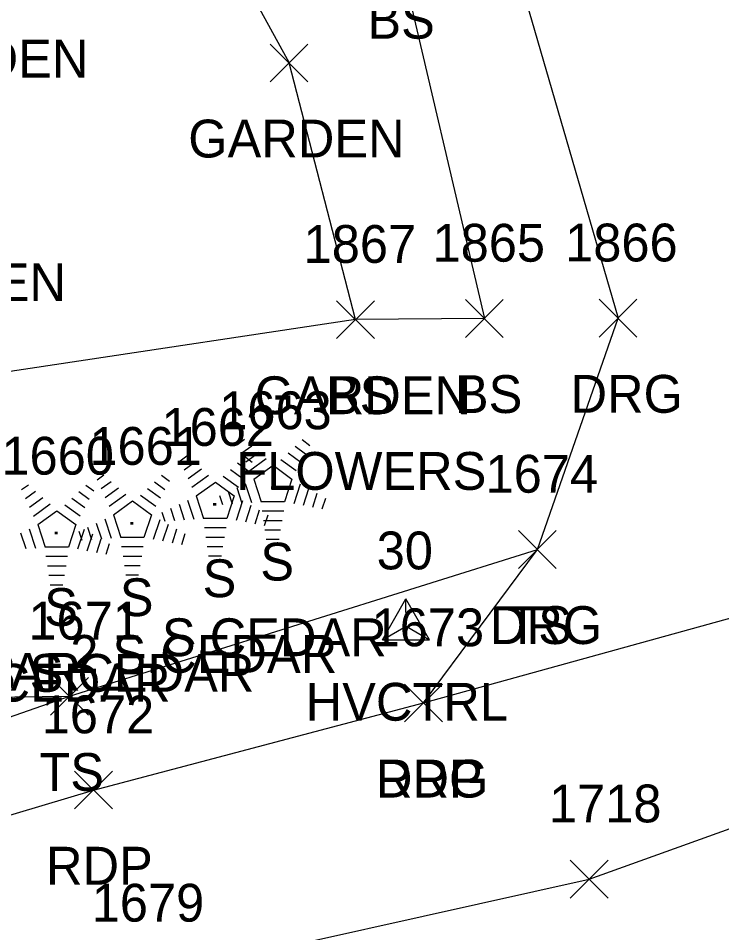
# Model space of a CAD drawing. Extents: x 1499292 to 1501024, y 534584 to 538043.
# Drawn here: x 1499990.32 to 1500027.52, y 537630.09 to 537678.44 of the extents above; entities that cross this region are included whole.
import ezdxf

# ---------------------------------------------------------------- set-up
doc = ezdxf.new("R2010")
doc.units = 0
for name, color, linetype in [('C_A', 7, 'Continuous'), ('C_I', 7, 'Continuous'), ('CPSM', 7, 'Continuous'), ('L_A', 7, 'Continuous'), ('L_C', 7, 'Continuous'), ('L_I', 7, 'Continuous'), ('L_TIC', 7, 'Continuous'), ('LAPB', 7, 'Continuous'), ('LELB', 7, 'Continuous'), ('LTC', 7, 'Continuous'), ('P_A', 7, 'Continuous'), ('P_I', 7, 'Continuous'), ('P_TIC', 7, 'Continuous'), ('PET', 7, 'Continuous'), ('PRC', 7, 'Continuous'), ('R_A', 7, 'Continuous'), ('R_I', 7, 'Continuous'), ('R_TIC', 7, 'Continuous'), ('RDG', 7, 'Continuous')]:
    doc.layers.add(name, color=color, linetype=linetype)

msp = doc.modelspace()

# ---------------------------------------------------------------- linework, layer by layer
at = {"layer": 'CPSM'}
for p, q in [((1500009.573, 537645.579), (1500010.823, 537647.744)), ((1500012.073, 537645.579), (1500010.823, 537647.744)), ((1500010.824, 537646.3), (1500010.823, 537647.744)), ((1500009.573, 537645.579), (1500010.824, 537646.3)), ((1500010.824, 537646.3), (1500010.824, 537646.3)), ((1500010.824, 537646.3), (1500012.073, 537645.579)), ((1500009.573, 537645.579), (1500012.073, 537645.579))]:
    msp.add_line(p, q, dxfattribs=at)
at = {"layer": 'L_TIC'}
for points in [[(1500003.638, 537675.076), (1500005.638, 537677.076)], [(1500005.638, 537675.076), (1500003.638, 537677.076)], [(1500003.638, 537675.076), (1500005.638, 537677.076)], [(1500005.638, 537675.076), (1500003.638, 537677.076)], [(1500007.149, 537661.504), (1500009.149, 537663.504)], [(1500009.149, 537661.504), (1500007.149, 537663.504)], [(1500007.149, 537661.504), (1500009.149, 537663.504)], [(1500009.149, 537661.504), (1500007.149, 537663.504)], [(1500007.149, 537661.504), (1500009.149, 537663.504)], [(1500009.149, 537661.504), (1500007.149, 537663.504)], [(1500013.967, 537661.567), (1500015.967, 537663.567)], [(1500015.967, 537661.567), (1500013.967, 537663.567)], [(1500016.771, 537649.353), (1500018.771, 537651.353)], [(1500018.771, 537649.353), (1500016.771, 537651.353)], [(1499992.025, 537641.588), (1499994.025, 537643.588)], [(1499994.025, 537641.588), (1499992.025, 537643.588)], [(1499992.025, 537641.588), (1499994.025, 537643.588)], [(1499994.025, 537641.588), (1499992.025, 537643.588)]]:
    msp.add_lwpolyline(points, dxfattribs=at)
at = {"layer": 'LAPB'}
for points in [[(1500008.149, 537662.504), (1499976.291, 537657.715), (1499960.955, 537655.744), (1499948.365, 537655.7), (1499944.782, 537667.728), (1499949.249, 537680.121), (1499961.303, 537682.861), (1499970.991, 537673.07), (1499976.904, 537664.777), (1499986.731, 537668.48), (1499987.916, 537680.302), (1499978.247, 537691.097), (1499980.645, 537701.007), (1499987.039, 537704.664), (1499995.658, 537692.472), (1500004.638, 537676.076)], [(1500008.149, 537662.504), (1500004.638, 537676.076)]]:
    msp.add_lwpolyline(points, dxfattribs=at)
at = {"layer": 'LELB'}
for points in [[(1500001.185, 537767.928), (1499990.808, 537751.601), (1499982.202, 537735.524), (1499991.302, 537713.767), (1500000.335, 537701.307), (1500010.339, 537682.356), (1500014.967, 537662.567), (1500008.149, 537662.504)], [(1499898.052, 537654.523), (1499910.254, 537639.037), (1499923.982, 537635.989), (1499941.209, 537637.588), (1499959.262, 537638.094), (1499978.567, 537642.414), (1499993.025, 537642.588)], [(1499875.628, 537635.389), (1499883.617, 537627.063), (1499893.294, 537615.077), (1499899.95, 537610.946), (1499909.177, 537610.062), (1499915.735, 537611.144), (1499937.582, 537622.682), (1499960.484, 537631.227), (1499993.025, 537642.588), (1500017.771, 537650.353)]]:
    msp.add_lwpolyline(points, dxfattribs=at)
at = {"layer": 'LTC'}
for p, q in [((1500001.927, 537655.918), (1500002.282, 537656.176)), ((1500005.326, 537656.158), (1500005.745, 537655.854)), ((1500002.137, 537655.453), (1500002.666, 537655.837)), ((1500002.347, 537654.987), (1500003.05, 537655.498)), ((1500004.954, 537655.81), (1500005.504, 537655.411)), ((1499998.877, 537655.037), (1499999.231, 537655.294)), ((1500002.275, 537655.277), (1500002.694, 537654.973)), ((1500002.556, 537654.521), (1500003.435, 537655.159)), ((1500004.212, 537655.113), (1500005.022, 537654.525)), ((1500004.584, 537655.462), (1500005.263, 537654.968)), ((1499999.086, 537654.571), (1499999.615, 537654.956)), ((1499999.296, 537654.106), (1500000, 537654.617)), ((1500001.533, 537654.581), (1500002.212, 537654.087)), ((1500001.904, 537654.929), (1500002.453, 537654.53)), ((1500002.781, 537654.066), (1500003.792, 537654.801)), ((1500003.792, 537654.801), (1500004.79, 537654.076)), ((1499994.496, 537654.034), (1499994.851, 537654.292)), ((1499997.895, 537654.275), (1499998.314, 537653.97)), ((1499999.505, 537653.64), (1500000.384, 537654.278)), ((1500001.162, 537654.232), (1500001.971, 537653.644)), ((1500002.781, 537654.066), (1500003.168, 537652.873)), ((1500004.79, 537654.076), (1500004.398, 537652.873)), ((1499990.496, 537653.517), (1499990.85, 537653.775)), ((1499993.894, 537653.758), (1499994.313, 537653.453)), ((1499994.706, 537653.569), (1499995.235, 537653.953)), ((1499994.916, 537653.103), (1499995.619, 537653.614)), ((1499997.153, 537653.578), (1499997.832, 537653.084)), ((1499997.524, 537653.926), (1499998.073, 537653.527)), ((1499999.73, 537653.185), (1500000.742, 537653.919)), ((1500000.742, 537653.919), (1500001.739, 537653.194)), ((1500001.871, 537653.631), (1500002.142, 537652.795)), ((1500002.326, 537653.847), (1500002.657, 537652.828)), ((1500005.227, 537653.805), (1500004.889, 537652.765)), ((1500005.672, 537653.554), (1500005.384, 537652.67)), ((1499990.705, 537653.052), (1499991.234, 537653.436)), ((1499990.915, 537652.586), (1499991.619, 537653.097)), ((1499993.152, 537653.061), (1499993.831, 537652.567)), ((1499993.523, 537653.41), (1499994.072, 537653.01)), ((1499995.125, 537652.637), (1499996.004, 537653.275)), ((1499996.781, 537653.23), (1499997.591, 537652.641)), ((1499999.73, 537653.185), (1500000.117, 537651.991)), ((1500000.96, 537653.197), (1500001.112, 537652.729)), ((1500001.739, 537653.194), (1500001.347, 537651.991)), ((1500001.415, 537653.414), (1500001.627, 537652.762)), ((1500006.116, 537653.304), (1500005.879, 537652.575)), ((1499991.124, 537652.12), (1499992.003, 537652.758)), ((1499992.781, 537652.713), (1499993.59, 537652.124)), ((1499995.35, 537652.182), (1499996.361, 537652.917)), ((1499996.361, 537652.917), (1499997.359, 537652.192)), ((1499998.82, 537652.749), (1499999.091, 537651.914)), ((1499999.275, 537652.966), (1499999.606, 537651.946)), ((1500002.176, 537652.924), (1500001.838, 537651.884)), ((1500002.621, 537652.673), (1500002.333, 537651.789)), ((1500004.398, 537652.873), (1500003.168, 537652.873)), ((1500006.56, 537653.054), (1500006.374, 537652.48)), ((1499991.349, 537651.665), (1499992.361, 537652.4)), ((1499992.361, 537652.4), (1499993.358, 537651.675)), ((1499995.35, 537652.182), (1499995.737, 537650.989)), ((1499997.359, 537652.192), (1499996.967, 537650.989)), ((1499997.909, 537652.316), (1499998.061, 537651.848)), ((1499998.365, 537652.533), (1499998.576, 537651.881)), ((1500003.065, 537652.423), (1500002.828, 537651.694)), ((1500004.36, 537652.373), (1500003.215, 537652.373)), ((1500003.51, 537652.173), (1500003.323, 537651.599)), ((1499991.349, 537651.665), (1499991.736, 537650.472)), ((1499993.358, 537651.675), (1499992.967, 537650.472)), ((1499994.44, 537651.747), (1499994.711, 537650.911)), ((1499994.895, 537651.963), (1499995.226, 537650.944)), ((1499997.796, 537651.921), (1499997.458, 537650.881)), ((1499998.241, 537651.67), (1499997.953, 537650.786)), ((1500001.347, 537651.991), (1500000.117, 537651.991)), ((1500004.276, 537651.873), (1500003.288, 537651.873)), ((1499990.439, 537651.23), (1499990.71, 537650.395)), ((1499990.894, 537651.446), (1499991.225, 537650.427)), ((1499993.795, 537651.404), (1499993.457, 537650.365)), ((1499993.529, 537651.313), (1499993.681, 537650.845)), ((1499994.24, 537651.154), (1499993.952, 537650.269)), ((1499993.984, 537651.53), (1499994.196, 537650.878)), ((1499998.685, 537651.42), (1499998.448, 537650.691)), ((1499999.129, 537651.17), (1499998.943, 537650.596)), ((1500001.309, 537651.491), (1500000.165, 537651.491)), ((1500004.192, 537651.373), (1500003.361, 537651.373)), ((1499994.684, 537650.904), (1499994.447, 537650.174)), ((1499995.129, 537650.653), (1499994.942, 537650.079)), ((1499996.967, 537650.989), (1499995.737, 537650.989)), ((1500001.225, 537650.991), (1500000.237, 537650.991)), ((1500004.109, 537650.873), (1500003.434, 537650.873)), ((1499992.967, 537650.472), (1499991.736, 537650.472)), ((1499996.929, 537650.489), (1499995.784, 537650.489)), ((1500001.142, 537650.491), (1500000.31, 537650.491)), ((1499992.928, 537649.972), (1499991.784, 537649.972)), ((1499996.845, 537649.989), (1499995.857, 537649.989)), ((1500001.058, 537649.991), (1500000.383, 537649.991)), ((1499992.844, 537649.472), (1499991.856, 537649.472)), ((1499996.761, 537649.489), (1499995.93, 537649.489)), ((1499992.761, 537648.972), (1499991.929, 537648.972)), ((1499996.678, 537648.989), (1499996.003, 537648.989)), ((1499992.677, 537648.472), (1499992.002, 537648.472))]:
    msp.add_line(p, q, dxfattribs=at)
at = {"layer": 'P_TIC'}
for points in [[(1500010.746, 537641.235), (1500012.746, 537643.235)], [(1500012.746, 537641.235), (1500010.746, 537643.235)], [(1499993.297, 537636.632), (1499995.297, 537638.632)], [(1499995.297, 537636.632), (1499993.297, 537638.632)], [(1500019.511, 537631.923), (1500021.511, 537633.923)], [(1500021.511, 537631.923), (1500019.511, 537633.923)]]:
    msp.add_lwpolyline(points, dxfattribs=at)
at = {"layer": 'PET'}
msp.add_lwpolyline([(1499877.015, 537630.958), (1499888.962, 537613.552), (1499899.651, 537608.634), (1499910.819, 537607.885), (1499917.779, 537609.039), (1499933.365, 537615.874), (1499940.692, 537619.272), (1499961.056, 537627.699), (1499994.297, 537637.632), (1500011.746, 537642.235), (1500032.99, 537648.112)], dxfattribs=at)
at = {"layer": 'PRC'}
msp.add_lwpolyline([(1499909.986, 537586.349), (1499926.303, 537596.084), (1499940.359, 537606.281), (1499956.988, 537614.658), (1499975.82, 537621.459), (1499996.949, 537627.676), (1500020.511, 537632.923), (1500051.029, 537643.891), (1500070.712, 537652.733), (1500093.189, 537667.353), (1500110.604, 537684.326), (1500128.972, 537704.003), (1500143.04, 537721.068)], dxfattribs=at)
at = {"layer": 'R_TIC'}
for points in [[(1500021.036, 537661.579), (1500023.036, 537663.579)], [(1500023.036, 537661.579), (1500021.036, 537663.579)], [(1500021.036, 537661.579), (1500023.036, 537663.579)], [(1500023.036, 537661.579), (1500021.036, 537663.579)], [(1500016.771, 537649.353), (1500018.771, 537651.353)], [(1500018.771, 537649.353), (1500016.771, 537651.353)], [(1500010.746, 537641.235), (1500012.746, 537643.235)], [(1500012.746, 537641.235), (1500010.746, 537643.235)]]:
    msp.add_lwpolyline(points, dxfattribs=at)
at = {"layer": 'RDG'}
for points in [[(1500063.799, 537780.312), (1500049.926, 537760.02), (1500040.89, 537749.673), (1500021.784, 537724.996), (1500010.572, 537724.396), (1499997.374, 537717.943), (1500005.783, 537701.6), (1500015.338, 537685.643), (1500022.036, 537662.579)], [(1500011.746, 537642.235), (1500017.771, 537650.353), (1500022.036, 537662.579)]]:
    msp.add_lwpolyline(points, dxfattribs=at)

# ---------------------------------------------------------------- texts
at = {"layer": 'C_A'}
msp.add_text('HVCTRL', height=2, dxfattribs=at).set_placement((1500005.517, 537641.3))
at = {"layer": 'C_I'}
msp.add_text('30', height=2, dxfattribs=at).set_placement((1500009.273, 537649.3))
at = {"layer": 'L_A'}
for s, p in [('BS', (1500008.78, 537677.356)), ('GARDEN', (1499982.585, 537675.302)), ('GARDEN', (1499999.307, 537671.076)), ('GARDEN', (1499999.307, 537671.076)), ('GARDEN', (1499981.4, 537663.48)), ('GARDEN', (1500002.819, 537657.504)), ('GARDEN', (1500002.819, 537657.504)), ('BS', (1500006.59, 537657.504)), ('BS', (1500013.408, 537657.567)), ('S', (1500003.118, 537648.71)), ('S', (1500000.067, 537647.829)), ('S', (1499995.687, 537646.826)), ('S', (1499991.686, 537646.309)), ('TS', (1500016.18, 537645.353)), ('TS', (1499991.434, 537637.588)), ('TS', (1499991.434, 537637.588))]:
    msp.add_text(s, height=2, dxfattribs=at).set_placement(p)
at = {"layer": 'L_C'}
for s, p in [('FLOWERS', (1500001.85, 537653.504)), ('FLOWERS', (1500001.85, 537653.504)), ('S.CEDAR', (1499997.913, 537644.71)), ('2 S.CEDAR', (1499993.067, 537643.829)), ('2 S.CEDAR', (1499979.508, 537642.879)), ('3 S.CEDAR', (1499988.687, 537642.826)), ('S.CEDAR', (1499986.482, 537642.309))]:
    msp.add_text(s, height=2, dxfattribs=at).set_placement(p)
at = {"layer": 'L_I'}
for s, p in [('1865', (1500012.227, 537665.567)), ('1867', (1500005.409, 537665.504)), ('1867', (1500005.409, 537665.504)), ('1867', (1500005.409, 537665.504)), ('1663', (1500000.945, 537656.71)), ('1662', (1499997.894, 537655.829)), ('1661', (1499994.081, 537654.826)), ('1660', (1499989.427, 537654.309)), ('1674', (1500015.031, 537653.353)), ('1671', (1499990.852, 537645.588)), ('1671', (1499990.852, 537645.588))]:
    msp.add_text(s, height=2, dxfattribs=at).set_placement(p)
at = {"layer": 'LTC'}
for p in [(1500003.675, 537653.814), (1500000.624, 537652.933), (1499996.244, 537651.93), (1499992.243, 537651.413)]:
    msp.add_text('.', height=1.037, rotation=270, dxfattribs=at).set_placement(p)
at = {"layer": 'P_A'}
for p in [(1500009.234, 537637.235), (1499991.785, 537632.632)]:
    msp.add_text('RDP', height=2, dxfattribs=at).set_placement(p)
at = {"layer": 'P_I'}
for s, p in [('1673', (1500009.006, 537645.235)), ('1672', (1499991.557, 537640.632)), ('1718', (1500018.385, 537635.923)), ('1679', (1499994.201, 537630.676))]:
    msp.add_text(s, height=2, dxfattribs=at).set_placement(p)
at = {"layer": 'R_A'}
for p in [(1500019.525, 537657.579), (1500019.525, 537657.579), (1500015.259, 537645.353), (1500009.234, 537637.235)]:
    msp.add_text('DRG', height=2, dxfattribs=at).set_placement(p)
at = {"layer": 'R_I'}
for s, p in [('1866', (1500019.241, 537665.579)), ('1866', (1500019.241, 537665.579)), ('1674', (1500015.031, 537653.353)), ('1673', (1500009.006, 537645.235))]:
    msp.add_text(s, height=2, dxfattribs=at).set_placement(p)

doc.saveas('drawing.dxf')
